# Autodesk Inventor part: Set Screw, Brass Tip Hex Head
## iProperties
Author: arennick
Comments: Thanks to S Dotson - This was created using his iPart as a template...
Shininess: 41.0
PropertySet Name: _Private Model Information
Created: 2001-02
Part Number: Set Screw, Brass Tip Hex Head
Material: Default
Document SubType Name: Modeling
Designer: arennick
Description: SetScrew, Brass Tip 1_4-20 UNFx0.5
Control State: 0
Master: False
Checked Out: False
PropertySet Name: Design Tracking Control
Density: 0.0
Volumn: 0.0
Area: 0.0
PropertySet Name: Model Information
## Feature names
1. Extrusion2
2. Extrusion3
3. Chamfer3
4. Chamfer2
5. Extrusion4
